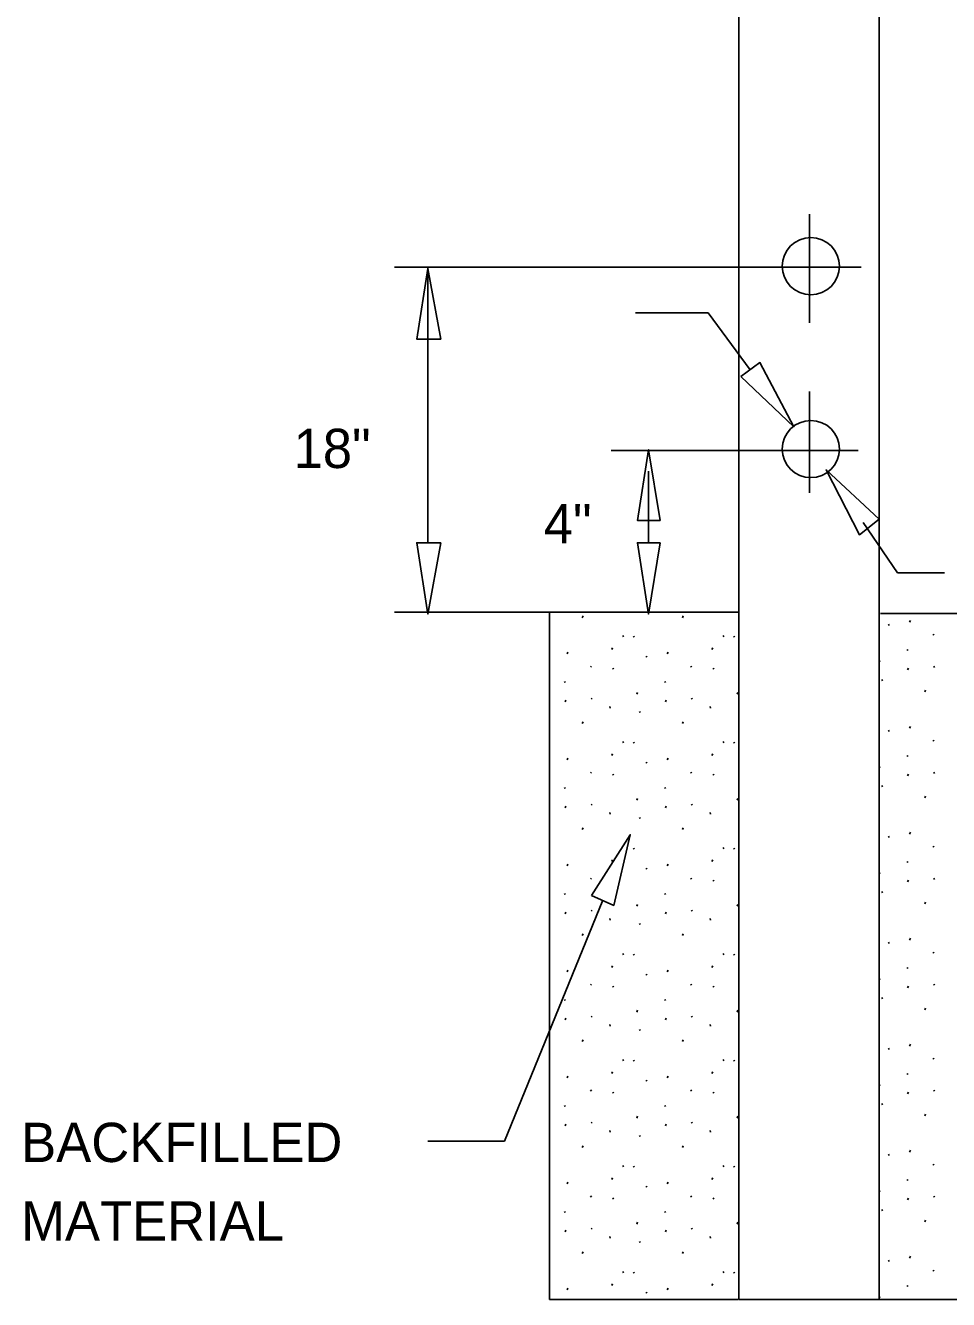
# Model space of a CAD drawing. Extents: x -2137320.7 to -2137313.2, y -2137946.3 to -2137936.1.
# Drawn here: x -2137319.973 to -2137318.564, y -2137943.591 to -2137941.645 of the extents above; entities that cross this region are included whole.
import ezdxf

# ---------------------------------------------------------------- set-up
doc = ezdxf.new("R2010")
doc.units = 0
for name, color, linetype in [('DETL-DIMS', 7, 'Continuous'), ('DETL-LINE', 7, 'Continuous'), ('DETL-NOTE', 7, 'Continuous'), ('DETL-PATT', 7, 'Continuous')]:
    doc.layers.add(name, color=color, linetype=linetype)

msp = doc.modelspace()

# ---------------------------------------------------------------- linework, layer by layer
at = {"layer": 'DETL-DIMS'}
for p, q in [((-2137318.776, -2137941.933), (-2137318.776, -2137942.099)), ((-2137318.6971, -2137942.014), (-2137319.41, -2137942.014)), ((-2137319.359, -2137942.435), (-2137319.359, -2137942.014)), ((-2137318.931, -2137942.084), (-2137319.042, -2137942.084)), ((-2137318.867, -2137942.171), (-2137318.931, -2137942.084)), ((-2137318.776, -2137942.204), (-2137318.776, -2137942.359)), ((-2137318.774, -2137942.294), (-2137319.079, -2137942.294)), ((-2137318.828, -2137942.294), (-2137318.7019, -2137942.294)), ((-2137319.022, -2137942.435), (-2137319.022, -2137942.326)), ((-2137318.694, -2137942.404), (-2137318.642, -2137942.481)), ((-2137318.642, -2137942.481), (-2137318.57, -2137942.481)), ((-2137319.092, -2137942.981), (-2137319.242, -2137943.349)), ((-2137319.242, -2137943.349), (-2137319.359, -2137943.349))]:
    msp.add_line(p, q, dxfattribs=at)
for points in [[(-2137319.339, -2137942.124), (-2137319.376, -2137942.124), (-2137319.359, -2137942.016)], [(-2137318.881, -2137942.181), (-2137318.852, -2137942.16), (-2137318.8, -2137942.258)], [(-2137319.004, -2137942.401), (-2137319.039, -2137942.401), (-2137319.022, -2137942.293)], [(-2137318.67, -2137942.399), (-2137318.7, -2137942.423), (-2137318.751, -2137942.324)], [(-2137319.339, -2137942.435), (-2137319.376, -2137942.435), (-2137319.359, -2137942.544)], [(-2137319.004, -2137942.435), (-2137319.039, -2137942.435), (-2137319.022, -2137942.544)], [(-2137319.109, -2137942.974), (-2137319.075, -2137942.989), (-2137319.05, -2137942.881)]]:
    msp.add_lwpolyline(points, close=True, dxfattribs=at)
at = {"layer": 'DETL-LINE'}
for p, q in [((-2137318.884, -2137940.149), (-2137318.884, -2137942.546)), ((-2137318.67, -2137942.546), (-2137318.67, -2137940.149)), ((-2137319.173, -2137942.541), (-2137319.41, -2137942.541)), ((-2137318.884, -2137942.541), (-2137319.173, -2137942.541)), ((-2137319.173, -2137942.541), (-2137319.173, -2137943.591)), ((-2137319.123, -2137942.541), (-2137318.975, -2137942.541)), ((-2137318.884, -2137942.664), (-2137318.884, -2137942.546)), ((-2137318.67, -2137942.656), (-2137318.67, -2137942.541)), ((-2137317.194, -2137942.543), (-2137318.668, -2137942.543)), ((-2137318.884, -2137942.664), (-2137318.884, -2137943.591)), ((-2137318.67, -2137943.591), (-2137318.67, -2137942.656)), ((-2137319.173, -2137943.591), (-2137318.885, -2137943.591)), ((-2137318.884, -2137943.591), (-2137318.67, -2137943.591)), ((-2137318.67, -2137943.591), (-2137318.369, -2137943.591))]:
    msp.add_line(p, q, dxfattribs=at)
for centre in [(-2137318.7742, -2137942.0127), (-2137318.7742, -2137942.292)]:
    msp.add_circle(centre, 0.0437, dxfattribs=at)
at = {"layer": 'DETL-PATT'}
for p, q in [((-2137319.1231, -2137942.5496), (-2137319.122, -2137942.547)), ((-2137318.9701, -2137942.5496), (-2137318.9689, -2137942.547)), ((-2137318.6234, -2137942.5563), (-2137318.6222, -2137942.5537)), ((-2137319.0613, -2137942.577), (-2137319.0601, -2137942.5788)), ((-2137319.0449, -2137942.5777), (-2137319.0437, -2137942.5794)), ((-2137318.9082, -2137942.577), (-2137318.907, -2137942.5788)), ((-2137318.8918, -2137942.5777), (-2137318.8907, -2137942.5794)), ((-2137318.6556, -2137942.5596), (-2137318.6544, -2137942.5613)), ((-2137318.5874, -2137942.5747), (-2137318.5863, -2137942.5764)), ((-2137319.0782, -2137942.5984), (-2137319.0771, -2137942.5958)), ((-2137318.9252, -2137942.5984), (-2137318.924, -2137942.5958)), ((-2137319.1464, -2137942.605), (-2137319.1453, -2137942.6024)), ((-2137319.0256, -2137942.6083), (-2137319.0244, -2137942.6101)), ((-2137318.9934, -2137942.605), (-2137318.9922, -2137942.6024)), ((-2137318.67, -2137942.6175), (-2137318.6688, -2137942.615)), ((-2137318.6272, -2137942.5982), (-2137318.626, -2137942.5999)), ((-2137319.1105, -2137942.6234), (-2137319.1093, -2137942.6251)), ((-2137319.0765, -2137942.6265), (-2137319.0753, -2137942.6282)), ((-2137318.9574, -2137942.6234), (-2137318.9562, -2137942.6251)), ((-2137318.9234, -2137942.6265), (-2137318.9222, -2137942.6282)), ((-2137318.6263, -2137942.6293), (-2137318.6251, -2137942.6267)), ((-2137318.5863, -2137942.6238), (-2137318.5852, -2137942.6255)), ((-2137319.1502, -2137942.6469), (-2137319.1491, -2137942.6487)), ((-2137318.9972, -2137942.6469), (-2137318.996, -2137942.6487)), ((-2137318.6658, -2137942.6442), (-2137318.6646, -2137942.6459)), ((-2137319.1094, -2137942.6725), (-2137319.1082, -2137942.6742)), ((-2137319.04, -2137942.6663), (-2137319.0388, -2137942.6637)), ((-2137318.9563, -2137942.6725), (-2137318.9552, -2137942.6742)), ((-2137318.8869, -2137942.6663), (-2137318.8858, -2137942.6637)), ((-2137318.6001, -2137942.6627), (-2137318.5989, -2137942.6601)), ((-2137319.1493, -2137942.6781), (-2137319.1481, -2137942.6755)), ((-2137319.0809, -2137942.6853), (-2137319.0806, -2137942.6879)), ((-2137319.0358, -2137942.6929), (-2137319.0346, -2137942.6946)), ((-2137318.9962, -2137942.6781), (-2137318.9951, -2137942.6755)), ((-2137318.9278, -2137942.6853), (-2137318.9275, -2137942.6879)), ((-2137319.1231, -2137942.7114), (-2137319.122, -2137942.7088)), ((-2137318.9701, -2137942.7114), (-2137318.9689, -2137942.7088)), ((-2137318.6556, -2137942.7215), (-2137318.6544, -2137942.7232)), ((-2137318.6234, -2137942.7181), (-2137318.6222, -2137942.7156)), ((-2137319.0613, -2137942.7389), (-2137319.0601, -2137942.7406)), ((-2137319.0449, -2137942.7396), (-2137319.0437, -2137942.7413)), ((-2137318.9082, -2137942.7389), (-2137318.907, -2137942.7406)), ((-2137318.8918, -2137942.7396), (-2137318.8907, -2137942.7413)), ((-2137318.5874, -2137942.7366), (-2137318.5863, -2137942.7383)), ((-2137319.1464, -2137942.7669), (-2137319.1453, -2137942.7643)), ((-2137319.0782, -2137942.7603), (-2137319.0771, -2137942.7577)), ((-2137319.0256, -2137942.7702), (-2137319.0244, -2137942.772)), ((-2137318.9934, -2137942.7669), (-2137318.9922, -2137942.7643)), ((-2137318.9252, -2137942.7603), (-2137318.924, -2137942.7577)), ((-2137318.6272, -2137942.7601), (-2137318.626, -2137942.7618)), ((-2137319.1105, -2137942.7853), (-2137319.1093, -2137942.787)), ((-2137319.0765, -2137942.7884), (-2137319.0753, -2137942.7901)), ((-2137318.9574, -2137942.7853), (-2137318.9562, -2137942.787)), ((-2137318.9234, -2137942.7884), (-2137318.9222, -2137942.7901)), ((-2137318.67, -2137942.7794), (-2137318.6688, -2137942.7768)), ((-2137318.6263, -2137942.7912), (-2137318.6251, -2137942.7886)), ((-2137318.5863, -2137942.7856), (-2137318.5852, -2137942.7874)), ((-2137319.1502, -2137942.8088), (-2137319.1491, -2137942.8106)), ((-2137318.9972, -2137942.8088), (-2137318.996, -2137942.8106)), ((-2137318.6658, -2137942.8061), (-2137318.6646, -2137942.8078)), ((-2137319.04, -2137942.8281), (-2137319.0388, -2137942.8256)), ((-2137318.8869, -2137942.8281), (-2137318.8858, -2137942.8256)), ((-2137318.6001, -2137942.8246), (-2137318.5989, -2137942.822)), ((-2137319.1493, -2137942.8399), (-2137319.1481, -2137942.8374)), ((-2137319.1094, -2137942.8344), (-2137319.1082, -2137942.8361)), ((-2137319.0809, -2137942.8472), (-2137319.0806, -2137942.8498)), ((-2137318.9962, -2137942.8399), (-2137318.9951, -2137942.8374)), ((-2137318.9563, -2137942.8344), (-2137318.9552, -2137942.8361)), ((-2137318.9278, -2137942.8472), (-2137318.9275, -2137942.8498)), ((-2137319.0358, -2137942.8548), (-2137319.0346, -2137942.8565)), ((-2137319.1231, -2137942.8733), (-2137319.122, -2137942.8707)), ((-2137318.9701, -2137942.8733), (-2137318.9689, -2137942.8707)), ((-2137318.6556, -2137942.8834), (-2137318.6544, -2137942.8851)), ((-2137318.6234, -2137942.88), (-2137318.6222, -2137942.8774)), ((-2137319.0449, -2137942.9015), (-2137319.0437, -2137942.9032)), ((-2137318.9082, -2137942.9008), (-2137318.907, -2137942.9025)), ((-2137318.8918, -2137942.9015), (-2137318.8907, -2137942.9032)), ((-2137318.5874, -2137942.8984), (-2137318.5863, -2137942.9002)), ((-2137319.1464, -2137942.9288), (-2137319.1453, -2137942.9262)), ((-2137319.0782, -2137942.9221), (-2137319.0771, -2137942.9195)), ((-2137318.9934, -2137942.9288), (-2137318.9922, -2137942.9262)), ((-2137318.9252, -2137942.9221), (-2137318.924, -2137942.9195)), ((-2137318.6272, -2137942.922), (-2137318.626, -2137942.9237)), ((-2137319.1105, -2137942.9472), (-2137319.1093, -2137942.9489)), ((-2137319.0256, -2137942.9321), (-2137319.0244, -2137942.9338)), ((-2137318.9574, -2137942.9472), (-2137318.9562, -2137942.9489)), ((-2137318.67, -2137942.9413), (-2137318.6688, -2137942.9387)), ((-2137318.5863, -2137942.9475), (-2137318.5852, -2137942.9493)), ((-2137318.9234, -2137942.9503), (-2137318.9222, -2137942.952)), ((-2137318.6263, -2137942.9531), (-2137318.6251, -2137942.9505)), ((-2137319.1502, -2137942.9707), (-2137319.1491, -2137942.9724)), ((-2137318.9972, -2137942.9707), (-2137318.996, -2137942.9724)), ((-2137318.6658, -2137942.968), (-2137318.6646, -2137942.9697)), ((-2137318.6001, -2137942.9865), (-2137318.5989, -2137942.9839)), ((-2137319.1493, -2137943.0018), (-2137319.1481, -2137942.9992)), ((-2137319.1094, -2137942.9963), (-2137319.1082, -2137942.998)), ((-2137319.04, -2137942.99), (-2137319.0388, -2137942.9874)), ((-2137318.9962, -2137943.0018), (-2137318.9951, -2137942.9992)), ((-2137318.9563, -2137942.9963), (-2137318.9552, -2137942.998)), ((-2137318.8869, -2137942.99), (-2137318.8858, -2137942.9874)), ((-2137319.0809, -2137943.0091), (-2137319.0806, -2137943.0116)), ((-2137319.0358, -2137943.0167), (-2137319.0346, -2137943.0184)), ((-2137318.9278, -2137943.0091), (-2137318.9275, -2137943.0116)), ((-2137319.1231, -2137943.0352), (-2137319.122, -2137943.0326)), ((-2137318.9701, -2137943.0352), (-2137318.9689, -2137943.0326)), ((-2137318.6234, -2137943.0419), (-2137318.6222, -2137943.0393)), ((-2137319.0613, -2137943.0627), (-2137319.0601, -2137943.0644)), ((-2137319.0449, -2137943.0634), (-2137319.0437, -2137943.0651)), ((-2137318.9082, -2137943.0627), (-2137318.907, -2137943.0644)), ((-2137318.8918, -2137943.0634), (-2137318.8907, -2137943.0651)), ((-2137318.6556, -2137943.0453), (-2137318.6544, -2137943.047)), ((-2137318.5874, -2137943.0603), (-2137318.5863, -2137943.0621)), ((-2137319.0782, -2137943.084), (-2137319.0771, -2137943.0814)), ((-2137318.9252, -2137943.084), (-2137318.924, -2137943.0814)), ((-2137318.6272, -2137943.0839), (-2137318.626, -2137943.0856)), ((-2137319.1464, -2137943.0906), (-2137319.1453, -2137943.088)), ((-2137319.0256, -2137943.094), (-2137319.0244, -2137943.0957)), ((-2137318.9934, -2137943.0906), (-2137318.9922, -2137943.088)), ((-2137318.67, -2137943.1032), (-2137318.6688, -2137943.1006)), ((-2137319.1105, -2137943.1091), (-2137319.1093, -2137943.1108)), ((-2137319.0765, -2137943.1122), (-2137319.0753, -2137943.1139)), ((-2137318.9574, -2137943.1091), (-2137318.9562, -2137943.1108)), ((-2137318.9234, -2137943.1122), (-2137318.9222, -2137943.1139)), ((-2137318.6263, -2137943.115), (-2137318.6251, -2137943.1124)), ((-2137318.5863, -2137943.1094), (-2137318.5852, -2137943.1111)), ((-2137319.1502, -2137943.1326), (-2137319.1491, -2137943.1343)), ((-2137318.9972, -2137943.1326), (-2137318.996, -2137943.1343)), ((-2137318.6658, -2137943.1299), (-2137318.6646, -2137943.1316)), ((-2137319.1493, -2137943.1637), (-2137319.1481, -2137943.1611)), ((-2137319.1094, -2137943.1581), (-2137319.1082, -2137943.1599)), ((-2137319.04, -2137943.1519), (-2137319.0388, -2137943.1493)), ((-2137318.9962, -2137943.1637), (-2137318.9951, -2137943.1611)), ((-2137318.9563, -2137943.1581), (-2137318.9552, -2137943.1599)), ((-2137318.8869, -2137943.1519), (-2137318.8858, -2137943.1493)), ((-2137318.6001, -2137943.1484), (-2137318.5989, -2137943.1458)), ((-2137319.0809, -2137943.1709), (-2137319.0806, -2137943.1735)), ((-2137319.0358, -2137943.1786), (-2137319.0346, -2137943.1803)), ((-2137318.9278, -2137943.1709), (-2137318.9275, -2137943.1735)), ((-2137319.1231, -2137943.1971), (-2137319.122, -2137943.1945)), ((-2137318.9701, -2137943.1971), (-2137318.9689, -2137943.1945)), ((-2137318.6556, -2137943.2072), (-2137318.6544, -2137943.2089)), ((-2137318.6234, -2137943.2038), (-2137318.6222, -2137943.2012)), ((-2137319.0613, -2137943.2246), (-2137319.0601, -2137943.2263)), ((-2137319.0449, -2137943.2252), (-2137319.0437, -2137943.227)), ((-2137318.9082, -2137943.2246), (-2137318.907, -2137943.2263)), ((-2137318.8918, -2137943.2252), (-2137318.8907, -2137943.227)), ((-2137318.5874, -2137943.2222), (-2137318.5863, -2137943.2239)), ((-2137319.1464, -2137943.2525), (-2137319.1453, -2137943.2499)), ((-2137319.0782, -2137943.2459), (-2137319.0771, -2137943.2433)), ((-2137319.0256, -2137943.2559), (-2137319.0244, -2137943.2576)), ((-2137318.9934, -2137943.2525), (-2137318.9922, -2137943.2499)), ((-2137318.9252, -2137943.2459), (-2137318.924, -2137943.2433)), ((-2137318.6272, -2137943.2458), (-2137318.626, -2137943.2475)), ((-2137319.1105, -2137943.2709), (-2137319.1093, -2137943.2727)), ((-2137319.0765, -2137943.2741), (-2137319.0753, -2137943.2758)), ((-2137318.9574, -2137943.2709), (-2137318.9562, -2137943.2727)), ((-2137318.9234, -2137943.2741), (-2137318.9222, -2137943.2758)), ((-2137318.67, -2137943.2651), (-2137318.6688, -2137943.2625)), ((-2137318.6263, -2137943.2769), (-2137318.6251, -2137943.2743)), ((-2137318.5863, -2137943.2713), (-2137318.5852, -2137943.273)), ((-2137319.1502, -2137943.2945), (-2137319.1491, -2137943.2962)), ((-2137318.9972, -2137943.2945), (-2137318.996, -2137943.2962)), ((-2137318.6658, -2137943.2917), (-2137318.6646, -2137943.2935)), ((-2137319.04, -2137943.3138), (-2137319.0388, -2137943.3112)), ((-2137318.8869, -2137943.3138), (-2137318.8858, -2137943.3112)), ((-2137318.6001, -2137943.3103), (-2137318.5989, -2137943.3077)), ((-2137319.1493, -2137943.3256), (-2137319.1481, -2137943.323)), ((-2137319.1094, -2137943.32), (-2137319.1082, -2137943.3218)), ((-2137319.0809, -2137943.3328), (-2137319.0806, -2137943.3354)), ((-2137318.9962, -2137943.3256), (-2137318.9951, -2137943.323)), ((-2137318.9563, -2137943.32), (-2137318.9552, -2137943.3218)), ((-2137318.9278, -2137943.3328), (-2137318.9275, -2137943.3354)), ((-2137319.1231, -2137943.359), (-2137319.122, -2137943.3564)), ((-2137319.0358, -2137943.3405), (-2137319.0346, -2137943.3422)), ((-2137318.9701, -2137943.359), (-2137318.9689, -2137943.3564)), ((-2137318.6556, -2137943.369), (-2137318.6544, -2137943.3708)), ((-2137318.6234, -2137943.3657), (-2137318.6222, -2137943.3631)), ((-2137319.0613, -2137943.3865), (-2137319.0601, -2137943.3882)), ((-2137319.0449, -2137943.3871), (-2137319.0437, -2137943.3888)), ((-2137318.9082, -2137943.3865), (-2137318.907, -2137943.3882)), ((-2137318.8918, -2137943.3871), (-2137318.8907, -2137943.3888)), ((-2137318.5874, -2137943.3841), (-2137318.5863, -2137943.3858)), ((-2137319.1464, -2137943.4144), (-2137319.1453, -2137943.4118)), ((-2137319.0782, -2137943.4078), (-2137319.0771, -2137943.4052)), ((-2137318.9934, -2137943.4144), (-2137318.9922, -2137943.4118)), ((-2137318.9252, -2137943.4078), (-2137318.924, -2137943.4052)), ((-2137318.6272, -2137943.4076), (-2137318.626, -2137943.4094)), ((-2137319.1105, -2137943.4328), (-2137319.1093, -2137943.4346)), ((-2137319.0256, -2137943.4178), (-2137319.0244, -2137943.4195)), ((-2137318.9574, -2137943.4328), (-2137318.9562, -2137943.4346)), ((-2137318.67, -2137943.427), (-2137318.6688, -2137943.4244)), ((-2137318.5863, -2137943.4332), (-2137318.5852, -2137943.4349)), ((-2137319.0765, -2137943.4359), (-2137319.0753, -2137943.4377)), ((-2137318.9234, -2137943.4359), (-2137318.9222, -2137943.4377)), ((-2137318.6658, -2137943.4536), (-2137318.6646, -2137943.4554)), ((-2137318.6263, -2137943.4388), (-2137318.6251, -2137943.4362)), ((-2137319.1502, -2137943.4564), (-2137319.1491, -2137943.4581)), ((-2137319.04, -2137943.4757), (-2137319.0388, -2137943.4731)), ((-2137318.9972, -2137943.4564), (-2137318.996, -2137943.4581)), ((-2137318.8869, -2137943.4757), (-2137318.8858, -2137943.4731)), ((-2137318.6001, -2137943.4721), (-2137318.5989, -2137943.4696)), ((-2137319.1493, -2137943.4875), (-2137319.1481, -2137943.4849)), ((-2137319.1094, -2137943.4819), (-2137319.1082, -2137943.4836)), ((-2137318.9962, -2137943.4875), (-2137318.9951, -2137943.4849)), ((-2137318.9563, -2137943.4819), (-2137318.9552, -2137943.4836)), ((-2137319.0809, -2137943.4947), (-2137319.0806, -2137943.4973)), ((-2137319.0358, -2137943.5023), (-2137319.0346, -2137943.5041)), ((-2137318.9278, -2137943.4947), (-2137318.9275, -2137943.4973)), ((-2137319.1231, -2137943.5209), (-2137319.122, -2137943.5183)), ((-2137318.9701, -2137943.5209), (-2137318.9689, -2137943.5183)), ((-2137318.6556, -2137943.5309), (-2137318.6544, -2137943.5327)), ((-2137318.6234, -2137943.5276), (-2137318.6222, -2137943.525)), ((-2137319.0613, -2137943.5484), (-2137319.0601, -2137943.5501)), ((-2137319.0449, -2137943.549), (-2137319.0437, -2137943.5507)), ((-2137318.9082, -2137943.5484), (-2137318.907, -2137943.5501)), ((-2137318.8918, -2137943.549), (-2137318.8907, -2137943.5507)), ((-2137318.5874, -2137943.546), (-2137318.5863, -2137943.5477)), ((-2137319.0782, -2137943.5697), (-2137319.0771, -2137943.5671)), ((-2137318.9252, -2137943.5697), (-2137318.924, -2137943.5671)), ((-2137318.6272, -2137943.5695), (-2137318.626, -2137943.5713)), ((-2137319.1464, -2137943.5763), (-2137319.1453, -2137943.5737)), ((-2137319.0256, -2137943.5797), (-2137319.0244, -2137943.5814)), ((-2137318.9934, -2137943.5763), (-2137318.9922, -2137943.5737)), ((-2137318.67, -2137943.5889), (-2137318.6688, -2137943.5863))]:
    msp.add_line(p, q, dxfattribs=at)

# ---------------------------------------------------------------- texts
at = {"layer": 'DETL-NOTE'}
for s, p in [('18"', (-2137319.564, -2137942.321)), ('4"', (-2137319.182, -2137942.436)), ('BACKFILLED', (-2137319.98, -2137943.381)), ('MATERIAL', (-2137319.98, -2137943.501))]:
    msp.add_text(s, height=0.06, dxfattribs=at).set_placement(p)

doc.saveas('drawing.dxf')
